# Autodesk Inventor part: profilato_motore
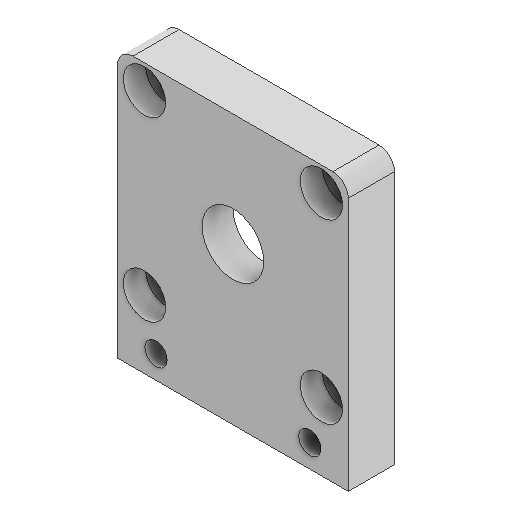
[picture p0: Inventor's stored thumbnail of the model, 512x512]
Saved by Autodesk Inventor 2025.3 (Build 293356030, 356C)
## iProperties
Created: 2025-11
Part Number: profilato_motore
Material: Generico
Document SubType Name: Modeling
Designer: R5800u
Density: 1 g/cm^3
Appearance: Default
Author: R5800u
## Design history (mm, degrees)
feature "Base3"
sketch "Schizzo1"
  geometry: L1 (30, 0)-(30, -5.7) reference; L2 (30, 0)-(0, 0) reference; L3 (0, -5.7)-(0, 0) reference; L4 (30, -5.7)-(0, -5.7) reference; C1 r 1.45 at (25, -2.7) reference; C2 r 1.45 at (5, -2.7) reference; 1 further point
extrude "Estrusione1" join sketch "Schizzo1" stored distance "d0" = 10; taper "d1" = 0 deg
node "Solido1"
node "Solido3"
node "Linea chiusa proiettata1"
